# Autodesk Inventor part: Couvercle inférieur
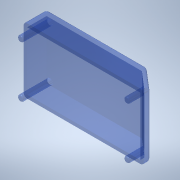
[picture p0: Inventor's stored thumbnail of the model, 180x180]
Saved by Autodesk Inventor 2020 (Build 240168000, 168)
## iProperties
Created: 2002-01
Part Number: Couvercle inférieur
Material: Polycarbonate, fumée
Document SubType Name: Modélisation
Designer: Philippe
Mass: 0.313675 g
Surface Area: 9.16512 cm^2
Volume: 0.261396 cm^3
Density: 1.2 g/cm^3
Appearance: Bleu (transparent/poli)
Shininess: 61.0
Angle Display Precision: 2
Document Length Units: 11269
Document Angle Units: 11279
Document Time Units: 11290
Document Mass Units: 11283
Document Length Units Precision: 3
Document Angle Units Precision: 2
Density: 0.0
Volumn: 0.0
Area: 0.0
PropertySet Name: Model Information
Control State: 0
Master: False
Checked Out: False
Author: Philippe
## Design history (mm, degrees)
sketch "Esquisse1"
  geometry: L1 (0, 0)-(21, 0); L2 (21, 0)-(21, 1); L3 (21, 1)-(17.5, 4); L4 (17.5, 4)-(0, 4); L5 (0, 4)-(0, 0)
  constraints: 10 end point, 2 parallel, 1 horizontal, 1 perpendicular, 1 other
  dimensions: "d0" = 4 distance of L4.end L1.start; "d2" = 1 distance of L1.end L2.end; "d3" = 17.5 distance of L3.end L4.end; "d4" = 21 distance of L1.start L1.end
extrude "Extrusion1" new body sketch "Esquisse1" stored distance "d5" = 11.4; taper "d6" = 0 deg
fillet "Congé1" dims "d7" = 0.6
feature "Coque1" dims "d8" = 0.6
node "Plan de construction1"
sketch "Esquisse2"
  geometry: L1 (-0.6, 10.8)-(-0.6, 0.6) reference; L2 (0, 0)-(19.8, 0) reference; C1 r 0.5 at (0.6, 10.2); C2 r 0.5 at (0.6, 1.2); C3 r 0.5 at (19.2, 1.2); C4 r 0.5 at (19.2, 10.2)
  constraints: 4 centre point, 3 equal radius, 2 horizontal alignment, 2 vertical alignment
  dimensions: "d10" = 1 diameter of C1; "d14" = 18.6 distance of C2.centre C3.centre; "d15" = 9 distance of C4.centre C3.centre; "d16" = 1.2 distance from line of L1 C2.centre; "d17" = 1.2 distance from line of C3.centre L2
extrude "Extrusion2" join sketch "Esquisse2" stored distance "d11" = 11.4; taper "d12" = 0 deg
fillet "Congé2" dims "d13" = 0.2
node "Solide1"
node "Corps solides"
node "Corps surfaciques"
other parameters: "d9" = 1.8
